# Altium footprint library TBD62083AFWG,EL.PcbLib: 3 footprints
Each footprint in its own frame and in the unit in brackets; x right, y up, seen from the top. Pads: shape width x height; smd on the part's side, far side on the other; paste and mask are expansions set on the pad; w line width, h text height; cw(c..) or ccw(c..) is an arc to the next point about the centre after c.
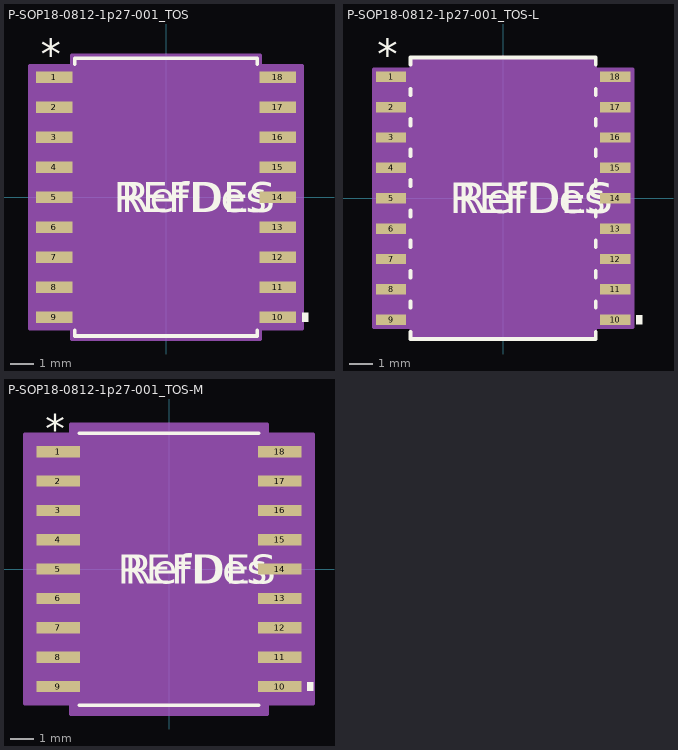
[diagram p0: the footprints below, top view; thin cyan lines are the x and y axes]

## P-SOP18-0812-1p27-001_TOS [mil]
pads (18):
  rect 61.46x19.13 smd paste+0 mask+0: 1(-186.52,200) 2(-186.52,150) 3(-186.52,100) 4(-186.52,50) 5(-186.52,0) 6(-186.52,-50) 7(-186.52,-100) 8(-186.52,-150) 9(-186.52,-200) 10(186.52,-200) 11(186.52,-150) 12(186.52,-100) 13(186.52,-50) 14(186.52,0) 15(186.52,50) 16(186.52,100) 17(186.52,150) 18(186.52,200)
Top Overlay:
  region: 227.25,-192.5 237.25,-192.5 237.25,-207.5 227.25,-207.5
  lines w6: -152.54,-222.25 -152.54,-231.67 152.54,-231.67 152.54,-222.25 ; -152.54,222.25 -152.54,231.67 152.54,231.67 152.54,222.25
  text "REFDES" at -87.5,-25 h50
  text "*" at -209.02,214.13 h50
  text "RefDes" at -75,-25 h50
Mechanical 13:
  lines w0: -12,226.67 ccw(c0,226.67) 12,226.67
  lines w1: -203.25,-208.56 -203.25,-191.44 -147.54,-191.44 -147.54,-208.56 -203.25,-208.56 ; -203.25,-158.56 -203.25,-141.44 -147.54,-141.44 -147.54,-158.56 -203.25,-158.56 ; -203.25,-108.56 -203.25,-91.44 -147.54,-91.44 -147.54,-108.56 -203.25,-108.56 ; -203.25,-58.56 -203.25,-41.44 -147.54,-41.44 -147.54,-58.56 -203.25,-58.56 ; -203.25,-8.56 -203.25,8.56 -147.54,8.56 -147.54,-8.56 -203.25,-8.56 ; -203.25,41.44 -203.25,58.56 -147.54,58.56 -147.54,41.44 -203.25,41.44 ; -203.25,91.44 -203.25,108.56 -147.54,108.56 -147.54,91.44 -203.25,91.44 ; -203.25,141.44 -203.25,158.56 -147.54,158.56 -147.54,141.44 -203.25,141.44 ; -203.25,191.44 -203.25,208.56 -147.54,208.56 -147.54,191.44 -203.25,191.44 ; -147.54,-226.67 147.54,-226.67 147.54,226.67 -147.54,226.67 -147.54,-226.67 ; 147.54,-208.56 147.54,-191.44 203.25,-191.44 203.25,-208.56 147.54,-208.56 ; 147.54,-158.56 147.54,-141.44 203.25,-141.44 203.25,-158.56 147.54,-158.56 ; 147.54,-108.56 147.54,-91.44 203.25,-91.44 203.25,-108.56 147.54,-108.56 ; 147.54,-58.56 147.54,-41.44 203.25,-41.44 203.25,-58.56 147.54,-58.56 ; 147.54,-8.56 147.54,8.56 203.25,8.56 203.25,-8.56 147.54,-8.56 ; 147.54,41.44 147.54,58.56 203.25,58.56 203.25,41.44 147.54,41.44 ; 147.54,91.44 147.54,108.56 203.25,108.56 203.25,91.44 147.54,91.44 ; 147.54,141.44 147.54,158.56 203.25,158.56 203.25,141.44 147.54,141.44 ; 147.54,191.44 147.54,208.56 203.25,208.56 203.25,191.44 147.54,191.44
  text "*" at -145.04,173.67 h50
  text "RefDes2" at -87.5,-25 h50
Mechanical 15:
  region: -157.54,-219.56 -227.25,-219.56 -227.25,219.56 -157.54,219.56 -157.54,236.67 157.54,236.67 157.54,219.56 227.25,219.56 227.25,-219.56 157.54,-219.56 157.54,-236.67 -157.54,-236.67
  lines w6: -227.25,-219.56 -227.25,219.56 -157.54,219.56 -157.54,236.67 157.54,236.67 157.54,219.56 227.25,219.56 227.25,-219.56 157.54,-219.56 157.54,-236.67 -157.54,-236.67 -157.54,-219.56 -227.25,-219.56
3D body "P-SOP18-0812-1p27-001_TOS.step": height 112.32, standoff 0, extent -203.27,-226.69 203.27,226.69

## P-SOP18-0812-1p27-001_TOS-L [mm]
pads (18):
  rect 1.256x0.435 smd paste+0 mask+0: 1(-4.687,5.08) 2(-4.687,3.81) 3(-4.687,2.54) 4(-4.687,1.27) 5(-4.687,0) 6(-4.687,-1.27) 7(-4.687,-2.54) 8(-4.687,-3.81) 9(-4.687,-5.08) 10(4.687,-5.08) 11(4.687,-3.81) 12(4.687,-2.54) 13(4.687,-1.27) 14(4.687,0) 15(4.687,1.27) 16(4.687,2.54) 17(4.687,3.81) 18(4.687,5.08)
Top Overlay:
  region: 5.569,-4.889 5.823,-4.889 5.823,-5.271 5.569,-5.271
  lines w0.152: -3.875,-5.575 -3.875,-5.884 3.875,-5.884 3.875,-5.575 ; -3.875,-4.585 -3.875,-4.305 ; -3.875,-3.315 -3.875,-3.035 ; -3.875,-2.045 -3.875,-1.765 ; -3.875,-0.775 -3.875,-0.495 ; -3.875,0.495 -3.875,0.775 ; -3.875,1.765 -3.875,2.045 ; -3.875,3.035 -3.875,3.315 ; -3.875,4.305 -3.875,4.585 ; -3.875,5.575 -3.875,5.884 3.875,5.884 3.875,5.575 ; 3.875,-4.585 3.875,-4.305 ; 3.875,-3.315 3.875,-3.035 ; 3.875,-2.045 3.875,-1.765 ; 3.875,-0.775 3.875,-0.495 ; 3.875,0.495 3.875,0.775 ; 3.875,1.765 3.875,2.045 ; 3.875,3.035 3.875,3.315 ; 3.875,4.305 3.875,4.585
  text "REFDES" at -2.222,-0.635 h1.27
  text "*" at -5.258,5.388 h1.27
  text "RefDes" at -1.905,-0.635 h1.27
Mechanical 13:
  lines w0: -0.305,5.757 ccw(c0,5.757) 0.305,5.757
  lines w0.025: -5.163,-5.298 -5.163,-4.862 -3.748,-4.862 -3.748,-5.298 -5.163,-5.298 ; -5.163,-4.028 -5.163,-3.592 -3.748,-3.592 -3.748,-4.028 -5.163,-4.028 ; -5.163,-2.758 -5.163,-2.322 -3.748,-2.322 -3.748,-2.758 -5.163,-2.758 ; -5.163,-1.488 -5.163,-1.052 -3.748,-1.052 -3.748,-1.488 -5.163,-1.488 ; -5.163,-0.218 -5.163,0.218 -3.748,0.218 -3.748,-0.218 -5.163,-0.218 ; -5.163,1.052 -5.163,1.488 -3.748,1.488 -3.748,1.052 -5.163,1.052 ; -5.163,2.322 -5.163,2.758 -3.748,2.758 -3.748,2.322 -5.163,2.322 ; -5.163,3.592 -5.163,4.028 -3.748,4.028 -3.748,3.592 -5.163,3.592 ; -5.163,4.862 -5.163,5.298 -3.748,5.298 -3.748,4.862 -5.163,4.862 ; -3.748,-5.757 3.748,-5.757 3.748,5.757 -3.748,5.757 -3.748,-5.757 ; 3.748,-5.298 3.748,-4.862 5.163,-4.862 5.163,-5.298 3.748,-5.298 ; 3.748,-4.028 3.748,-3.592 5.163,-3.592 5.163,-4.028 3.748,-4.028 ; 3.748,-2.758 3.748,-2.322 5.163,-2.322 5.163,-2.758 3.748,-2.758 ; 3.748,-1.488 3.748,-1.052 5.163,-1.052 5.163,-1.488 3.748,-1.488 ; 3.748,-0.218 3.748,0.218 5.163,0.218 5.163,-0.218 3.748,-0.218 ; 3.748,1.052 3.748,1.488 5.163,1.488 5.163,1.052 3.748,1.052 ; 3.748,2.322 3.748,2.758 5.163,2.758 5.163,2.322 3.748,2.322 ; 3.748,3.592 3.748,4.028 5.163,4.028 5.163,3.592 3.748,3.592 ; 3.748,4.862 3.748,5.298 5.163,5.298 5.163,4.862 3.748,4.862
  text "*" at -3.684,4.411 h1.27
  text "RefDes2" at -2.222,-0.635 h1.27
Mechanical 15:
  region: -3.849,-5.399 -5.416,-5.399 -5.416,5.399 -3.849,5.399 -3.849,5.859 3.849,5.859 3.849,5.399 5.416,5.399 5.416,-5.399 3.849,-5.399 3.849,-5.859 -3.849,-5.859
  lines w0.152: -5.416,-5.399 -5.416,5.399 -3.849,5.399 -3.849,5.859 3.849,5.859 3.849,5.399 5.416,5.399 5.416,-5.399 3.849,-5.399 3.849,-5.859 -3.849,-5.859 -3.849,-5.399 -5.416,-5.399
3D body "P-SOP18-0812-1p27-001_TOS.step": height 2.85, standoff 0, extent -5.163,-5.758 5.163,5.758

## P-SOP18-0812-1p27-001_TOS-M [mil]
pads (18):
  rect 73.46x19.13 smd paste+0 mask+0: 1(-188.52,200) 2(-188.52,150) 3(-188.52,100) 4(-188.52,50) 5(-188.52,0) 6(-188.52,-50) 7(-188.52,-100) 8(-188.52,-150) 9(-188.52,-200) 10(188.52,-200) 11(188.52,-150) 12(188.52,-100) 13(188.52,-50) 14(188.52,0) 15(188.52,50) 16(188.52,100) 17(188.52,150) 18(188.52,200)
Top Overlay:
  region: 235.25,-192.5 245.25,-192.5 245.25,-207.5 235.25,-207.5
  lines w6: -152.54,-231.67 152.54,-231.67 ; -152.54,231.67 152.54,231.67
  text "REFDES" at -87.5,-25 h50
  text "*" at -211.02,214.13 h50
  text "RefDes" at -75,-25 h50
Mechanical 13:
  lines w0: -12,226.67 ccw(c0,226.67) 12,226.67
  lines w1: -203.25,-208.56 -203.25,-191.44 -147.54,-191.44 -147.54,-208.56 -203.25,-208.56 ; -203.25,-158.56 -203.25,-141.44 -147.54,-141.44 -147.54,-158.56 -203.25,-158.56 ; -203.25,-108.56 -203.25,-91.44 -147.54,-91.44 -147.54,-108.56 -203.25,-108.56 ; -203.25,-58.56 -203.25,-41.44 -147.54,-41.44 -147.54,-58.56 -203.25,-58.56 ; -203.25,-8.56 -203.25,8.56 -147.54,8.56 -147.54,-8.56 -203.25,-8.56 ; -203.25,41.44 -203.25,58.56 -147.54,58.56 -147.54,41.44 -203.25,41.44 ; -203.25,91.44 -203.25,108.56 -147.54,108.56 -147.54,91.44 -203.25,91.44 ; -203.25,141.44 -203.25,158.56 -147.54,158.56 -147.54,141.44 -203.25,141.44 ; -203.25,191.44 -203.25,208.56 -147.54,208.56 -147.54,191.44 -203.25,191.44 ; -147.54,-226.67 147.54,-226.67 147.54,226.67 -147.54,226.67 -147.54,-226.67 ; 147.54,-208.56 147.54,-191.44 203.25,-191.44 203.25,-208.56 147.54,-208.56 ; 147.54,-158.56 147.54,-141.44 203.25,-141.44 203.25,-158.56 147.54,-158.56 ; 147.54,-108.56 147.54,-91.44 203.25,-91.44 203.25,-108.56 147.54,-108.56 ; 147.54,-58.56 147.54,-41.44 203.25,-41.44 203.25,-58.56 147.54,-58.56 ; 147.54,-8.56 147.54,8.56 203.25,8.56 203.25,-8.56 147.54,-8.56 ; 147.54,41.44 147.54,58.56 203.25,58.56 203.25,41.44 147.54,41.44 ; 147.54,91.44 147.54,108.56 203.25,108.56 203.25,91.44 147.54,91.44 ; 147.54,141.44 147.54,158.56 203.25,158.56 203.25,141.44 147.54,141.44 ; 147.54,191.44 147.54,208.56 203.25,208.56 203.25,191.44 147.54,191.44
  text "*" at -145.04,173.67 h50
  text "RefDes2" at -87.5,-25 h50
Mechanical 15:
  region: -167.54,-229.56 -245.25,-229.56 -245.25,229.56 -167.54,229.56 -167.54,246.67 167.54,246.67 167.54,229.56 245.25,229.56 245.25,-229.56 167.54,-229.56 167.54,-246.67 -167.54,-246.67
  lines w6: -245.25,-229.56 -245.25,229.56 -167.54,229.56 -167.54,246.67 167.54,246.67 167.54,229.56 245.25,229.56 245.25,-229.56 167.54,-229.56 167.54,-246.67 -167.54,-246.67 -167.54,-229.56 -245.25,-229.56
3D body "P-SOP18-0812-1p27-001_TOS.step": height 112.32, standoff 0, extent -203.27,-226.69 203.27,226.69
